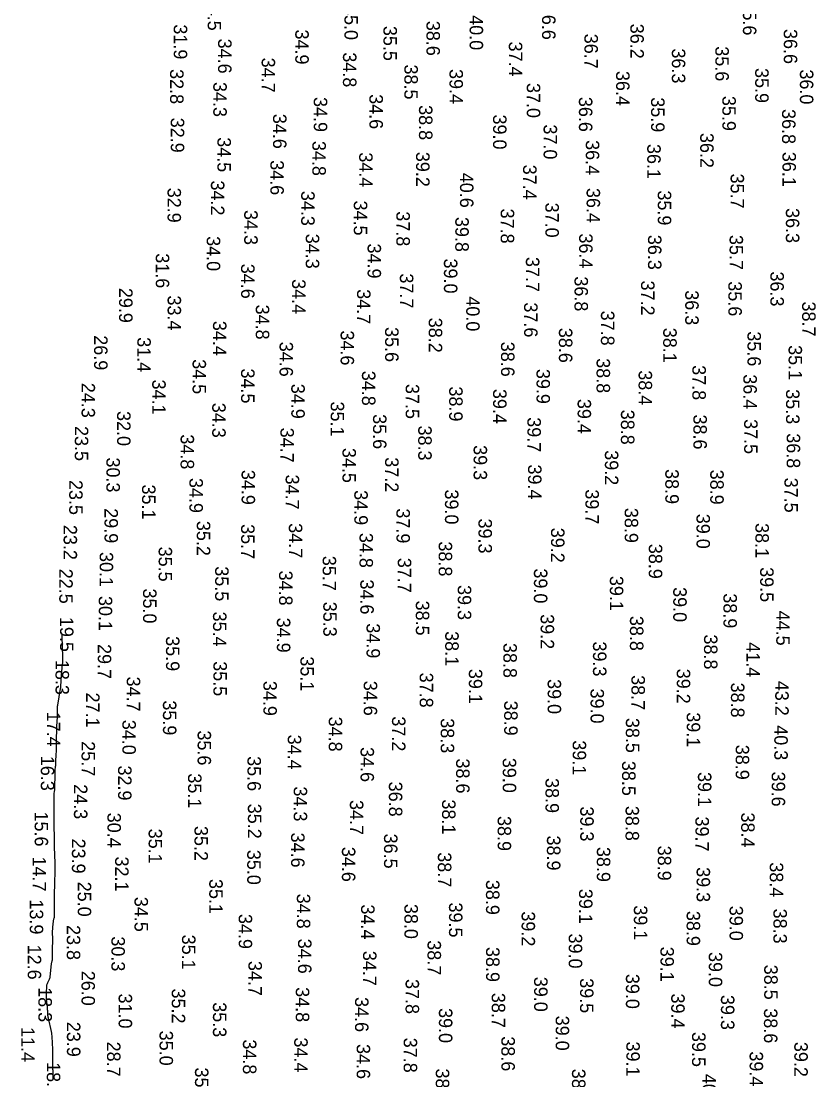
# Model space of a CAD drawing. Extents: x 1178573 to 1187098, y 693282 to 751751.
# Drawn here: x 1178887 to 1179626, y 706267 to 707251 of the extents above; entities that cross this region are included whole.
import ezdxf

# ---------------------------------------------------------------- set-up
doc = ezdxf.new("R2010")
doc.units = 0
doc.layers.add('V-HYDS-MINR', color=7, linetype='Continuous')
doc.layers.add('V-HYDS-SOUN', color=7, linetype='Continuous')

msp = doc.modelspace()

# ---------------------------------------------------------------- linework, layer by layer
at = {"layer": 'V-HYDS-MINR'}
msp.add_lwpolyline([(1178917.24, 706267.06), (1178917.21, 706268.01), (1178917.19, 706268.97), (1178917.17, 706269.93), (1178917.09, 706273.75), (1178917.07, 706274.71), (1178917.05, 706275.66), (1178917.03, 706276.62), (1178917.01, 706277.58), (1178916.83, 706284.91), (1178916.8, 706286.32), (1178916.78, 706287.74), (1178916.77, 706289.15), (1178916.77, 706290.57), (1178916.77, 706296.48), (1178916.76, 706297.77), (1178916.73, 706299.05), (1178916.68, 706300.34), (1178916.62, 706301.62), (1178916.31, 706306.77), (1178916.2, 706308.05), (1178916.05, 706309.32), (1178915.84, 706310.59), (1178915.59, 706311.85), (1178912.78, 706324.38), (1178912.61, 706325.21), (1178912.48, 706326.05), (1178912.37, 706326.89), (1178912.31, 706327.74), (1178912.11, 706331.15), (1178912.06, 706332), (1178912, 706332.85), (1178911.92, 706333.7), (1178911.85, 706334.54), (1178911.1, 706342.17), (1178910.99, 706343.55), (1178910.93, 706344.94), (1178910.92, 706346.34), (1178910.97, 706347.73), (1178911.33, 706354.58), (1178911.41, 706355.32), (1178911.57, 706356.04), (1178911.81, 706356.74), (1178912.13, 706357.42), (1178913.57, 706360.08), (1178913.89, 706360.75), (1178914.15, 706361.45), (1178914.33, 706362.17), (1178914.44, 706362.91), (1178915.3, 706371.84), (1178915.38, 706372.59), (1178915.49, 706373.34), (1178915.62, 706374.08), (1178915.77, 706374.82), (1178916.42, 706377.77), (1178916.55, 706378.51), (1178916.64, 706379.26), (1178916.68, 706380), (1178916.67, 706380.76), (1178916.52, 706384.19), (1178916.49, 706385.01), (1178916.48, 706385.84), (1178916.48, 706386.66), (1178916.5, 706387.49), (1178916.81, 706397.73), (1178916.82, 706398.28), (1178916.81, 706398.83), (1178916.79, 706399.39), (1178916.75, 706399.94), (1178916.55, 706402.15), (1178916.52, 706402.71), (1178916.51, 706403.26), (1178916.52, 706403.81), (1178916.55, 706404.37), (1178917.28, 706412.49), (1178917.34, 706413.1), (1178917.42, 706413.7), (1178917.53, 706414.31), (1178917.65, 706414.91), (1178918.27, 706417.72), (1178918.34, 706418.11), (1178918.39, 706418.5), (1178918.41, 706418.9), (1178918.41, 706419.3), (1178918.35, 706420.9), (1178918.34, 706421.3), (1178918.33, 706421.7), (1178918.33, 706422.1), (1178918.33, 706422.5), (1178918.57, 706443.63), (1178918.57, 706443.8), (1178918.57, 706443.97), (1178918.58, 706444.15), (1178918.59, 706444.32), (1178918.63, 706445), (1178918.63, 706445.17), (1178918.64, 706445.34), (1178918.65, 706445.52), (1178918.65, 706445.69), (1178918.92, 706465.16), (1178918.92, 706465.46), (1178918.93, 706465.75), (1178918.93, 706466.05), (1178918.94, 706466.35), (1178918.96, 706467.53), (1178918.96, 706467.83), (1178918.96, 706468.13), (1178918.96, 706468.42), (1178918.95, 706468.72), (1178918.46, 706483.43), (1178918.45, 706483.87), (1178918.43, 706484.31), (1178918.42, 706484.74), (1178918.42, 706485.18), (1178918.38, 706487.69), (1178918.38, 706487.75), (1178918.37, 706487.81), (1178918.37, 706487.87), (1178918.37, 706487.92), (1178918.35, 706488.16), (1178918.35, 706488.22), (1178918.34, 706488.28), (1178918.34, 706488.34), (1178918.34, 706488.4), (1178918.28, 706507.26), (1178918.27, 706507.71), (1178918.27, 706508.16), (1178918.27, 706508.61), (1178918.27, 706509.06), (1178918.28, 706511.72), (1178918.28, 706511.73), (1178918.28, 706511.75), (1178918.28, 706511.76), (1178918.27, 706511.77), (1178918.27, 706511.82), (1178918.27, 706511.84), (1178918.26, 706511.85), (1178918.26, 706511.86), (1178918.26, 706511.87), (1178918.26, 706512.06), (1178918.26, 706512.1), (1178918.25, 706512.13), (1178918.25, 706512.17), (1178918.25, 706512.2), (1178918.11, 706529.58), (1178918.12, 706530.34), (1178918.15, 706531.1), (1178918.19, 706531.86), (1178918.26, 706532.62), (1178918.59, 706535.64), (1178918.66, 706536.4), (1178918.72, 706537.15), (1178918.76, 706537.91), (1178918.78, 706538.67), (1178918.97, 706550.91), (1178918.99, 706551.84), (1178919.03, 706552.77), (1178919.08, 706553.7), (1178919.16, 706554.63), (1178919.48, 706558.34), (1178919.55, 706559.27), (1178919.62, 706560.19), (1178919.68, 706561.12), (1178919.73, 706562.05), (1178920.11, 706570.27), (1178920.17, 706571.58), (1178920.2, 706572.89), (1178920.23, 706574.2), (1178920.24, 706575.51), (1178920.24, 706580.96), (1178920.25, 706582.17), (1178920.27, 706583.38), (1178920.3, 706584.59), (1178920.35, 706585.8), (1178920.56, 706590.64), (1178920.61, 706591.85), (1178920.66, 706593.06), (1178920.71, 706594.27), (1178920.76, 706595.47), (1178921.11, 706604.62), (1178921.14, 706605.51), (1178921.16, 706606.4), (1178921.18, 706607.3), (1178921.18, 706608.19), (1178921.18, 706611.76), (1178921.2, 706612.65), (1178921.25, 706613.54), (1178921.35, 706614.42), (1178921.47, 706615.31), (1178924.07, 706630.94), (1178924.18, 706631.65), (1178924.27, 706632.37), (1178924.34, 706633.08), (1178924.39, 706633.8), (1178924.54, 706636.68), (1178924.58, 706637.4), (1178924.63, 706638.12), (1178924.68, 706638.84), (1178924.74, 706639.56), (1178926.01, 706653.76), (1178926.05, 706654.3), (1178926.09, 706654.85), (1178926.13, 706655.39), (1178926.16, 706655.94), (1178926.26, 706658.12), (1178926.28, 706658.66), (1178926.28, 706659.21), (1178926.28, 706659.76), (1178926.26, 706660.3), (1178925.49, 706679.04), (1178925.48, 706679.24), (1178925.48, 706679.45), (1178925.47, 706679.66), (1178925.47, 706679.86), (1178925.46, 706680.69), (1178925.45, 706680.9), (1178925.42, 706681.1), (1178925.39, 706681.3), (1178925.34, 706681.5), (1178924.92, 706683.02)], dxfattribs=at)

# ---------------------------------------------------------------- texts
at = {"layer": 'V-HYDS-SOUN'}
for s, p in [('34.5 ', (1179060.8, 707274.79)), ('35.0 ', (1179187.93, 707266.13)), ('36.6 ', (1179371.59, 707266.31)), ('35.6 ', (1179558.27, 707270.38)), ('40.0 ', (1179304.26, 707256.68)), ('31.9 ', (1179029.27, 707248.14)), ('34.9 ', (1179142.23, 707243.38)), ('35.5 ', (1179224.19, 707246.71)), ('38.6 ', (1179264.17, 707251.45)), ('36.2 ', (1179453.66, 707248.76)), ('36.6 ', (1179596.26, 707243.84)), ('34.6 ', (1179070.47, 707234.88)), ('36.7 ', (1179410.96, 707239.44)), ('37.4 ', (1179340.71, 707232.17)), ('36.3 ', (1179492.22, 707225.79)), ('35.6 ', (1179532.64, 707227.76)), ('34.7 ', (1179110.96, 707217.2)), ('34.8 ', (1179186.56, 707222.15)), ('32.8 ', (1179025.86, 707206.57)), ('38.5 ', (1179243.61, 707210.85)), ('39.4 ', (1179285.56, 707206.61)), ('36.4 ', (1179440.42, 707204.87)), ('35.9 ', (1179569.66, 707207.58)), ('36.0 ', (1179611.22, 707206.28)), ('34.3 ', (1179066.04, 707194.59)), ('37.0 ', (1179357.41, 707193.65)), ('34.9 ', (1179159.42, 707180.62)), ('34.6 ', (1179211.15, 707183.27)), ('36.6 ', (1179405.84, 707180.75)), ('35.9 ', (1179472.91, 707180.39)), ('35.9 ', (1179539.15, 707181.63)), ('34.6 ', (1179121.55, 707165)), ('38.8 ', (1179257.19, 707173.07)), ('39.0 ', (1179326.05, 707164.35)), ('36.8 ', (1179594.66, 707169.43)), ('32.9 ', (1179026.49, 707161.39)), ('37.0 ', (1179373, 707155.14)), ('36.2 ', (1179518.56, 707147.22)), ('34.5 ', (1179069.89, 707143.23)), ('34.8 ', (1179158.11, 707139.8)), ('36.4 ', (1179412.24, 707140.57)), ('36.1 ', (1179469.33, 707136.97)), ('34.4 ', (1179201.61, 707129.18)), ('39.2 ', (1179254.52, 707129.66)), ('36.1 ', (1179595.02, 707129.66)), ('34.6 ', (1179119.06, 707121.89)), ('37.4 ', (1179353.94, 707117.7)), ('40.6 ', (1179295.31, 707110.21)), ('35.7 ', (1179546.82, 707109.46)), ('32.9 ', (1179023.5, 707096.3)), ('34.2 ', (1179063.83, 707103.06)), ('36.4 ', (1179412.99, 707096.08)), ('34.3 ', (1179147.73, 707093.38)), ('35.9 ', (1179479.14, 707093.81)), ('34.3 ', (1179094.78, 707075.6)), ('34.5 ', (1179196.63, 707084.4)), ('37.8 ', (1179333.14, 707076.91)), ('37.0 ', (1179374.67, 707082.46)), ('36.3 ', (1179598.19, 707077.4)), ('37.8 ', (1179236.2, 707074.38)), ('39.8 ', (1179290.95, 707069.13)), ('34.0 ', (1179059.97, 707051.3)), ('34.3 ', (1179152, 707053.52)), ('36.4 ', (1179406.07, 707053.82)), ('36.3 ', (1179470.04, 707052.5)), ('35.7 ', (1179545.86, 707052.4)), ('34.9 ', (1179209.42, 707044.46)), ('31.6 ', (1179012.6, 707035.37)), ('39.0 ', (1179280.38, 707030.5)), ('37.7 ', (1179356.56, 707031.93)), ('34.6 ', (1179091.86, 707025.63)), ('37.7 ', (1179239.43, 707016.67)), ('36.3 ', (1179583.79, 707018.48)), ('34.4 ', (1179139.3, 707011.37)), ('36.8 ', (1179401.75, 707013.92)), ('37.2 ', (1179463.6, 707010.04)), ('35.6 ', (1179544.72, 707009.32)), ('29.9 ', (1178978.49, 707003.22)), ('34.7 ', (1179199.61, 707002.01)), ('36.3 ', (1179504.66, 707001.02)), ('33.4 ', (1179023.56, 706996.18)), ('34.8 ', (1179105.55, 706987.64)), ('40.0 ', (1179301.08, 706995.33)), ('37.6 ', (1179354.92, 706989.71)), ('38.7 ', (1179613.32, 706990.53)), ('37.8 ', (1179426.32, 706982.03)), ('34.4 ', (1179065.75, 706972.56)), ('38.2 ', (1179266.26, 706975.46)), ('26.9 ', (1178955.26, 706959.16)), ('31.4 ', (1178995.44, 706957.37)), ('34.6 ', (1179184.35, 706963.66)), ('35.6 ', (1179225.72, 706966.8)), ('38.6 ', (1179387.24, 706966.08)), ('38.1 ', (1179484.2, 706966.14)), ('35.6 ', (1179562.5, 706962.83)), ('34.6 ', (1179127.62, 706953.16)), ('38.6 ', (1179333.43, 706953.16)), ('35.1 ', (1179600.7, 706950)), ('38.8 ', (1179422.25, 706937.83)), ('34.5 ', (1179046.76, 706936.93)), ('34.5 ', (1179091.87, 706928.3)), ('39.9 ', (1179366.41, 706927.89)), ('37.8 ', (1179511.29, 706931.37)), ('34.1 ', (1179009.3, 706918.01)), ('34.8 ', (1179204.21, 706926.16)), ('38.4 ', (1179461.32, 706926.59)), ('36.4 ', (1179558.69, 706922.89)), ('24.3 ', (1178943.6, 706914.97)), ('34.9 ', (1179138.53, 706914.05)), ('37.5 ', (1179244.86, 706913.9)), ('38.9 ', (1179285.28, 706911.59)), ('39.4 ', (1179326.08, 706909.3)), ('35.3 ', (1179598.32, 706909.03)), ('39.4 ', (1179404.62, 706900.02)), ('32.0 ', (1178976.61, 706888.73)), ('34.3 ', (1179065.03, 706896.4)), ('35.1 ', (1179175.14, 706897.6)), ('38.8 ', (1179444.89, 706889.97)), ('35.6 ', (1179214.47, 706885.83)), ('39.7 ', (1179357.97, 706882.98)), ('38.6 ', (1179512.24, 706885.51)), ('37.5 ', (1179559.42, 706881.25)), ('23.5 ', (1178937.34, 706874.79)), ('34.7 ', (1179128.44, 706873.27)), ('38.3 ', (1179256.49, 706875.24)), ('34.8 ', (1179035.64, 706867.07)), ('36.8 ', (1179598.96, 706868.05)), ('34.5 ', (1179186.1, 706854.45)), ('39.3 ', (1179307.97, 706857.03)), ('39.2 ', (1179429.97, 706852.3)), ('30.3 ', (1178966.7, 706845.58)), ('37.2 ', (1179225.71, 706845.77)), ('34.9 ', (1179092.33, 706834.06)), ('34.7 ', (1179133.27, 706829.67)), ('39.4 ', (1179358.56, 706839.06)), ('38.9 ', (1179486.13, 706834.78)), ('38.9 ', (1179527.9, 706834.23)), ('23.5 ', (1178932.1, 706824.66)), ('35.1 ', (1178999.81, 706820.44)), ('34.9 ', (1179043.84, 706826.52)), ('37.5 ', (1179596.89, 706826.79)), ('34.9 ', (1179197.09, 706815.2)), ('39.0 ', (1179281.33, 706815.83)), ('39.7 ', (1179411.88, 706815.95)), ('29.9 ', (1178964.9, 706798.4)), ('37.9 ', (1179236.23, 706798.24)), ('38.9 ', (1179448.37, 706798.7)), ('39.0 ', (1179515.12, 706793.23)), ('23.2 ', (1178926.89, 706782.88)), ('35.2 ', (1179050.71, 706786.62)), ('35.7 ', (1179091.9, 706783.64)), ('34.7 ', (1179136.25, 706784.49)), ('39.3 ', (1179312.5, 706788.82)), ('39.2 ', (1179379.91, 706780.25)), ('38.1 ', (1179569.86, 706784.58)), ('34.8 ', (1179201.94, 706775.47)), ('35.5 ', (1179015.23, 706762.68)), ('38.8 ', (1179275.5, 706767.53)), ('38.9 ', (1179470.78, 706765.3)), ('30.1 ', (1178960.44, 706757.68)), ('35.7 ', (1179167.68, 706754.14)), ('37.7 ', (1179237.5, 706752.3)), ('22.5 ', (1178922.88, 706742.15)), ('35.5 ', (1179067.76, 706744.41)), ('39.0 ', (1179364.01, 706742.44)), ('39.5 ', (1179574.29, 706743.62)), ('34.8 ', (1179127.14, 706740.43)), ('34.6 ', (1179202.66, 706732.16)), ('39.1 ', (1179434.59, 706735.47)), ('35.0 ', (1179000.75, 706723.8)), ('39.3 ', (1179293.24, 706726.98)), ('39.0 ', (1179493.5, 706725.05)), ('30.1 ', (1178959.56, 706716.83)), ('35.3 ', (1179168.27, 706711.49)), ('38.5 ', (1179254.27, 706712.52)), ('38.9 ', (1179540.17, 706719.3)), ('35.4 ', (1179065.75, 706702.28)), ('44.5 ', (1179589.25, 706703.2)), ('19.5 ', (1178923.57, 706697.36)), ('34.9 ', (1179125.14, 706696.66)), ('39.2 ', (1179370.26, 706699.91)), ('38.8 ', (1179453.26, 706698.3)), ('34.9 ', (1179208.44, 706691.41)), ('38.1 ', (1179281.61, 706684.12)), ('29.7 ', (1178958.69, 706672.15)), ('35.9 ', (1179022.06, 706679.47)), ('38.8 ', (1179335.64, 706673.14)), ('39.3 ', (1179418.9, 706674.55)), ('38.8 ', (1179522.09, 706681.04)), ('41.4 ', (1179561.51, 706673.8)), ('18.3 ', (1178919.42, 706657.36)), ('35.5 ', (1179066.18, 706656.16)), ('35.1 ', (1179147.03, 706660.73)), ('37.8 ', (1179257.88, 706645.55)), ('39.1 ', (1179303.55, 706649.05)), ('38.7 ', (1179454.66, 706643.25)), ('39.2 ', (1179496.81, 706649.22)), ('34.7 ', (1178985.63, 706641.9)), ('34.9 ', (1179112.57, 706637.9)), ('34.6 ', (1179205.84, 706638)), ('39.0 ', (1179376.77, 706639.58)), ('38.8 ', (1179547.15, 706636.29)), ('43.2 ', (1179588.31, 706638)), ('27.1 ', (1178947.78, 706627.07)), ('39.0 ', (1179416.63, 706630.79)), ('35.9 ', (1179019.23, 706619.79)), ('38.9 ', (1179336.39, 706619.53)), ('17.4 ', (1178911.32, 706609.3)), ('34.8 ', (1179173.37, 706604.67)), ('37.2 ', (1179232.11, 706604.93)), ('38.3 ', (1179277.39, 706603.19)), ('38.5 ', (1179449.48, 706603.47)), ('39.1 ', (1179506.05, 706608.73)), ('34.0 ', (1178981.53, 706601.72)), ('40.3 ', (1179587.43, 706596.66)), ('35.6 ', (1179051.44, 706591.87)), ('34.4 ', (1179135.27, 706587.91)), ('25.7 ', (1178943.57, 706581.83)), ('34.6 ', (1179202.89, 706576.39)), ('39.1 ', (1179400.04, 706582.64)), ('38.9 ', (1179551.55, 706578.52)), ('16.3 ', (1178905.74, 706568.28)), ('35.6 ', (1179097.8, 706567.95)), ('38.6 ', (1179291.73, 706565.79)), ('39.0 ', (1179335.04, 706566.36)), ('38.5 ', (1179445.97, 706563.57)), ('32.9 ', (1178977.54, 706559.26)), ('35.1 ', (1179042.56, 706551.94)), ('36.8 ', (1179229.21, 706544.23)), ('38.9 ', (1179374.78, 706547.58)), ('39.1 ', (1179516.45, 706553.18)), ('39.6 ', (1179585, 706553.55)), ('24.3 ', (1178936.52, 706541.87)), ('34.3 ', (1179140.75, 706539.77)), ('34.7 ', (1179192.98, 706527.17)), ('38.1 ', (1179278.65, 706527.72)), ('15.6 ', (1178900, 706516.48)), ('30.4 ', (1178967.65, 706515.37)), ('35.2 ', (1179098.18, 706523.73)), ('39.3 ', (1179407.08, 706521.2)), ('38.8 ', (1179449.19, 706521.73)), ('38.4 ', (1179556.66, 706515.54)), ('38.9 ', (1179330.32, 706512.28)), ('39.7 ', (1179514.14, 706511.85)), ('35.1 ', (1179005.92, 706500.53)), ('35.2 ', (1179048.55, 706503.06)), ('34.6 ', (1179138.35, 706496.89)), ('36.5 ', (1179224.68, 706495.92)), ('23.9 ', (1178934.62, 706491.31)), ('38.9 ', (1179376.12, 706494.17)), ('35.0 ', (1179097.54, 706480.86)), ('34.6 ', (1179185.56, 706483.64)), ('38.7 ', (1179274.77, 706478.58)), ('38.9 ', (1179422.51, 706483.54)), ('38.9 ', (1179479.11, 706484.72)), ('14.7 ', (1178898.03, 706474.68)), ('32.1 ', (1178974.81, 706474.64)), ('38.4 ', (1179583.23, 706469.24)), ('39.3 ', (1179515.22, 706464.77)), ('25.0 ', (1178940.06, 706451.26)), ('35.1 ', (1179062.28, 706453.77)), ('38.9 ', (1179319.46, 706452.93)), ('34.5 ', (1178992.82, 706437.19)), ('34.8 ', (1179143.68, 706440.1)), ('39.1 ', (1179405.95, 706444.59)), ('13.9 ', (1178895.45, 706434.75)), ('34.4 ', (1179203.41, 706430.1)), ('38.0 ', (1179243.67, 706430.6)), ('39.5 ', (1179285.08, 706431.91)), ('39.1 ', (1179456.9, 706429.27)), ('39.0 ', (1179545.83, 706428.86)), ('38.3 ', (1179586.61, 706426.22)), ('34.9 ', (1179089.64, 706421.24)), ('39.2 ', (1179352.55, 706423.66)), ('38.9 ', (1179505.95, 706424.09)), ('23.8 ', (1178929.9, 706410.97)), ('30.3 ', (1178971.36, 706400.43)), ('35.1 ', (1179036.95, 706402)), ('34.6 ', (1179144.78, 706398.24)), ('38.7 ', (1179265.16, 706396.79)), ('39.0 ', (1179396.39, 706403.04)), ('12.6 ', (1178893.57, 706392.72)), ('34.7 ', (1179205.18, 706386.98)), ('38.9 ', (1179319.56, 706390.56)), ('39.1 ', (1179481.61, 706390.78)), ('34.7 ', (1179098.72, 706377.6)), ('39.0 ', (1179526.57, 706385.88)), ('26.0 ', (1178943.54, 706368.46)), ('38.5 ', (1179578.06, 706374.07)), ('37.8 ', (1179244.76, 706360.77)), ('39.0 ', (1179364.2, 706362.85)), ('39.5 ', (1179406.87, 706361.54)), ('39.0 ', (1179449.51, 706365.54)), ('18.3 ', (1178903.51, 706353.22)), ('31.0 ', (1178978.05, 706347.3)), ('35.2 ', (1179027.45, 706351.97)), ('34.8 ', (1179142.73, 706353.22)), ('38.7 ', (1179324.83, 706347.91)), ('39.4 ', (1179491.63, 706347.3)), ('35.3 ', (1179065.71, 706339.21)), ('34.6 ', (1179197.77, 706344)), ('39.3 ', (1179537.83, 706345.97)), ('39.0 ', (1179275.72, 706333.78)), ('38.6 ', (1179577.82, 706333.54)), ('23.9 ', (1178930, 706321.01)), ('39.0 ', (1179384.25, 706326.69)), ('11.4 ', (1178887.47, 706316.13)), ('35.0 ', (1179016.08, 706312.78)), ('39.5 ', (1179511, 706311.57)), ('28.7 ', (1178967.26, 706302.57)), ('34.8 ', (1179093.58, 706304.67)), ('34.4 ', (1179141.24, 706306.48)), ('34.6 ', (1179199.31, 706300.34)), ('37.8 ', (1179242.99, 706306.21)), ('38.6 ', (1179333.79, 706307.52)), ('39.1 ', (1179449.91, 706302.69)), ('39.2 ', (1179606.02, 706302.33)), ('39.4 ', (1179564.47, 706293.52)), ('18.6 ', (1178911.32, 706283.54)), ('35.2 ', (1179049, 706278.55)), ('38.7 ', (1179272.83, 706277.63)), ('38.9 ', (1179399.39, 706277.37)), ('40.0 ', (1179520.67, 706272.66))]:
    msp.add_text(s, height=12.5, rotation=270, dxfattribs=at).set_placement(p)

doc.saveas('drawing.dxf')
